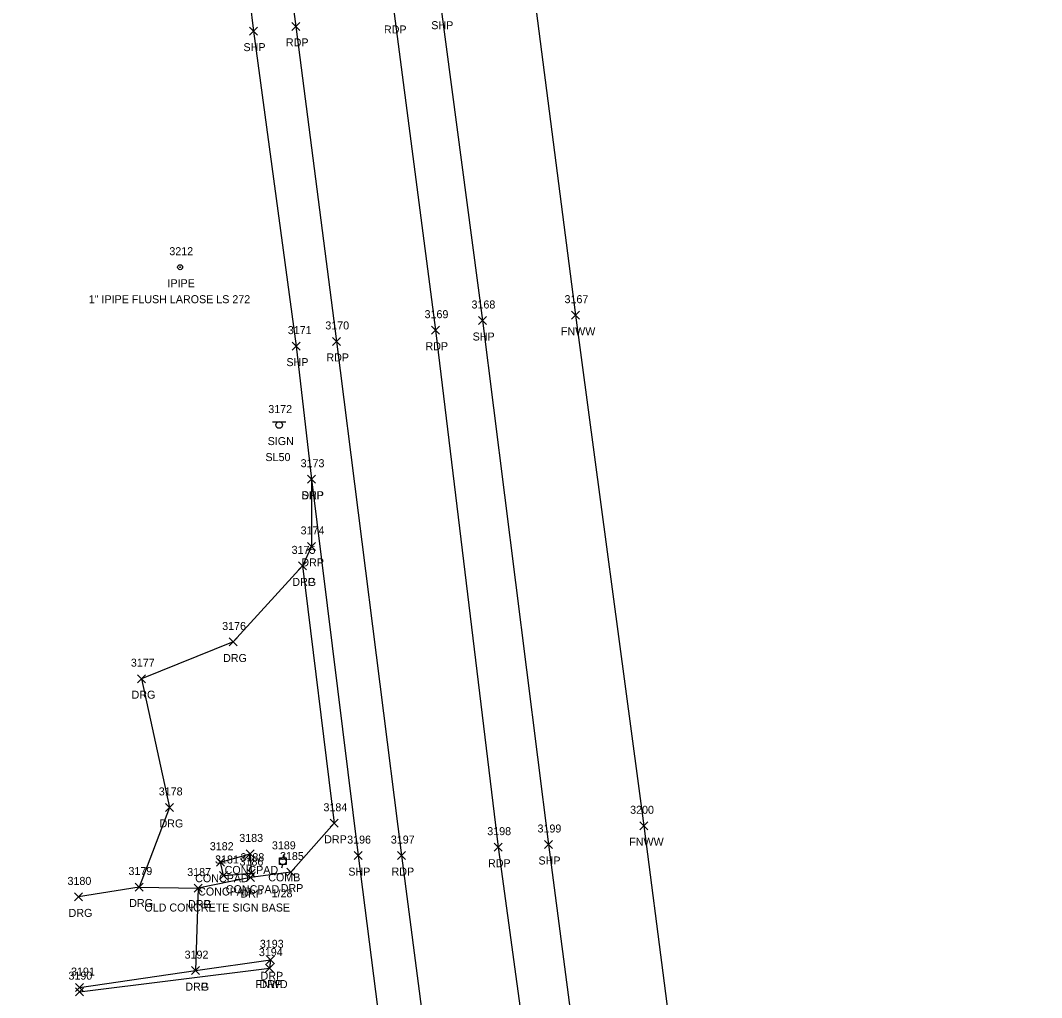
# Model space of a CAD drawing. Extents: x 1443071 to 1445292, y 614024 to 622563.
# Drawn here: x 1444280.5 to 1444535.7, y 616523.8 to 616767.9 of the extents above; entities that cross this region are included whole.
import ezdxf

# ---------------------------------------------------------------- set-up
doc = ezdxf.new("R2010")
doc.units = 0
for name, color, linetype in [('L_A', 7, 'Continuous'), ('L_C', 7, 'Continuous'), ('L_I', 7, 'Continuous'), ('L_TIC', 7, 'Continuous'), ('LFNC', 7, 'Continuous'), ('LS', 7, 'Continuous'), ('M_A', 7, 'Continuous'), ('M_C', 7, 'Continuous'), ('M_I', 7, 'Continuous'), ('MPIP', 7, 'Continuous'), ('P_A', 7, 'Continuous'), ('P_I', 7, 'Continuous'), ('P_TIC', 7, 'Continuous'), ('PET', 7, 'Continuous'), ('PSP', 7, 'Continuous'), ('R_A', 7, 'Continuous'), ('R_I', 7, 'Continuous'), ('R_TIC', 7, 'Continuous'), ('RDG', 7, 'Continuous'), ('RDP', 7, 'Continuous'), ('S_A', 7, 'Continuous'), ('S_C', 7, 'Continuous'), ('S_I', 7, 'Continuous'), ('SSGN', 7, 'Continuous'), ('U_A', 7, 'Continuous'), ('U_C', 7, 'Continuous'), ('U_I', 7, 'Continuous'), ('UP', 7, 'Continuous')]:
    doc.layers.add(name, color=color, linetype=linetype)

msp = doc.modelspace()

# ---------------------------------------------------------------- linework, layer by layer
at = {"layer": 'L_TIC'}
for points in [[(1444418.22, 616693.29), (1444420.22, 616695.29)], [(1444420.22, 616693.29), (1444418.22, 616695.29)], [(1444435.3, 616565.7), (1444437.3, 616567.7)], [(1444437.3, 616565.7), (1444435.3, 616567.7)], [(1444336.88, 616558.67), (1444338.88, 616560.67)], [(1444338.88, 616558.67), (1444336.88, 616560.67)], [(1444329.52, 616556.6), (1444331.52, 616558.6)], [(1444331.52, 616556.6), (1444329.52, 616558.6)], [(1444330.26, 616553.28), (1444332.26, 616555.28)], [(1444332.26, 616553.28), (1444330.26, 616555.28)], [(1444330.26, 616553.28), (1444332.26, 616555.28)], [(1444332.26, 616553.28), (1444330.26, 616555.28)], [(1444337.19, 616553.85), (1444339.19, 616555.85)], [(1444339.19, 616553.85), (1444337.19, 616555.85)], [(1444337.19, 616553.85), (1444339.19, 616555.85)], [(1444339.19, 616553.85), (1444337.19, 616555.85)], [(1444341.78, 616530.14), (1444343.78, 616532.14)], [(1444343.78, 616530.14), (1444341.78, 616532.14)], [(1444294.29, 616524.25), (1444296.29, 616526.25)], [(1444296.29, 616524.25), (1444294.29, 616526.25)]]:
    msp.add_lwpolyline(points, dxfattribs=at)
at = {"layer": 'LFNC'}
for points in [[(1444444.21, 617032.59), (1444396.73, 617023.1), (1444383.68, 617022.43), (1444396.85, 616893.79), (1444402.65, 616848.17), (1444409.06, 616773.1), (1444419.22, 616694.29), (1444436.3, 616566.7), (1444446.44, 616488.05), (1444452.89, 616451.02), (1444456.99, 616417.96)], [(1444295.29, 616525.25), (1444342.78, 616531.14)]]:
    msp.add_lwpolyline(points, dxfattribs=at)
at = {"layer": 'LS'}
for points in [[(1444331.26, 616554.28), (1444330.52, 616557.6), (1444337.88, 616559.67), (1444338.19, 616554.85)], [(1444331.26, 616554.28), (1444338.19, 616554.85)]]:
    msp.add_lwpolyline(points, dxfattribs=at)
at = {"layer": 'MPIP'}
for radius in [0.625, 0.0833]:
    msp.add_circle((1444320.42, 616706.28), radius, dxfattribs=at)
at = {"layer": 'P_TIC'}
for points in [[(1444348.36, 616765.46), (1444350.36, 616767.46)], [(1444350.36, 616765.46), (1444348.36, 616767.46)], [(1444337.72, 616764.27), (1444339.72, 616766.27)], [(1444339.72, 616764.27), (1444337.72, 616766.27)], [(1444394.97, 616691.96), (1444396.97, 616693.96)], [(1444396.97, 616691.96), (1444394.97, 616693.96)], [(1444383.25, 616689.54), (1444385.25, 616691.54)], [(1444385.25, 616689.54), (1444383.25, 616691.54)], [(1444358.48, 616686.73), (1444360.48, 616688.73)], [(1444360.48, 616686.73), (1444358.48, 616688.73)], [(1444348.45, 616685.56), (1444350.45, 616687.56)], [(1444350.45, 616685.56), (1444348.45, 616687.56)], [(1444352.22, 616652.3), (1444354.22, 616654.3)], [(1444354.22, 616652.3), (1444352.22, 616654.3)], [(1444411.43, 616561.03), (1444413.43, 616563.03)], [(1444413.43, 616561.03), (1444411.43, 616563.03)], [(1444398.86, 616560.36), (1444400.86, 616562.36)], [(1444400.86, 616560.36), (1444398.86, 616562.36)], [(1444363.91, 616558.25), (1444365.91, 616560.25)], [(1444365.91, 616558.25), (1444363.91, 616560.25)], [(1444374.76, 616558.26), (1444376.76, 616560.26)], [(1444376.76, 616558.26), (1444374.76, 616560.26)]]:
    msp.add_lwpolyline(points, dxfattribs=at)
at = {"layer": 'PET'}
for points in [[(1444290.04, 617226.49), (1444293.29, 617200.68), (1444305.86, 617102.26), (1444318.1, 617012.36), (1444328.61, 616929.53), (1444340.48, 616832.7), (1444349.36, 616766.46), (1444359.48, 616687.73), (1444375.76, 616559.26), (1444386.72, 616474.82), (1444392.98, 616424.11), (1444399.64, 616374.74), (1444405.35, 616331.68), (1444416.25, 616246.74), (1444430.45, 616134.64), (1444440.68, 616052.2), (1444460.71, 615897.87), (1444469.48, 615825.17), (1444479.32, 615749.85), (1444490.82, 615663.43), (1444501.1, 615593.99)], [(1444314.9, 617227.6), (1444331.28, 617099.37), (1444342.74, 617014.98), (1444353.45, 616933.43), (1444365.99, 616834.42), (1444373.87, 616769.68), (1444384.25, 616690.54), (1444399.86, 616561.36), (1444411.32, 616477.78), (1444418.43, 616426.72), (1444433.04, 616320.39), (1444440.5, 616248.61), (1444455.15, 616137.88), (1444465.57, 616054.84), (1444485.3, 615900.9), (1444494.14, 615826.26), (1444503.74, 615751.94), (1444515.41, 615666.64), (1444525.64, 615597.72)]]:
    msp.add_lwpolyline(points, dxfattribs=at)
at = {"layer": 'PSP'}
for points in [[(1444325.72, 617229.34), (1444331.18, 617190.03), (1444341.63, 617111.11), (1444353.65, 617016.1), (1444364.55, 616934.22), (1444377.14, 616835.48), (1444385.64, 616770.75), (1444395.97, 616692.96), (1444412.43, 616562.03), (1444423.01, 616481.11), (1444430.88, 616420.51), (1444443.11, 616323.39), (1444448.99, 616268.44), (1444454, 616230.8), (1444465.61, 616141.36), (1444476.5, 616056.13), (1444483.28, 615998.72), (1444489.46, 615946.55), (1444495.54, 615902.14), (1444505.18, 615827.19), (1444514.81, 615753.2), (1444525.85, 615667.7), (1444535.69, 615600.77)], [(1444280.5, 617226.12), (1444283.66, 617200.61), (1444293.17, 617127.11), (1444296.38, 617100.83), (1444308.28, 617010.91), (1444318.74, 616928.98), (1444325.56, 616872.02), (1444335.05, 616795.34), (1444338.72, 616765.27), (1444349.45, 616686.56), (1444353.22, 616653.3), (1444364.91, 616559.25), (1444375.85, 616473.62), (1444383.24, 616422.24), (1444388.01, 616382.64), (1444395.12, 616329.81), (1444406.01, 616244.88), (1444420.16, 616134.13), (1444430.49, 616051.12), (1444450.17, 615896.86), (1444459.96, 615823.48), (1444469.66, 615749), (1444481.34, 615661.86), (1444491.6, 615592.34)]]:
    msp.add_lwpolyline(points, dxfattribs=at)
at = {"layer": 'R_TIC'}
for points in [[(1444352.22, 616652.3), (1444354.22, 616654.3)], [(1444354.22, 616652.3), (1444352.22, 616654.3)], [(1444352.22, 616635.51), (1444354.22, 616637.51)], [(1444354.22, 616635.51), (1444352.22, 616637.51)], [(1444349.96, 616630.64), (1444351.96, 616632.64)], [(1444351.96, 616630.64), (1444349.96, 616632.64)], [(1444349.96, 616630.64), (1444351.96, 616632.64)], [(1444351.96, 616630.64), (1444349.96, 616632.64)], [(1444332.67, 616611.63), (1444334.67, 616613.63)], [(1444334.67, 616611.63), (1444332.67, 616613.63)], [(1444309.79, 616602.46), (1444311.79, 616604.46)], [(1444311.79, 616602.46), (1444309.79, 616604.46)], [(1444316.77, 616570.29), (1444318.77, 616572.29)], [(1444318.77, 616570.29), (1444316.77, 616572.29)], [(1444357.93, 616566.33), (1444359.93, 616568.33)], [(1444359.93, 616566.33), (1444357.93, 616568.33)], [(1444347.07, 616554.14), (1444349.07, 616556.14)], [(1444349.07, 616554.14), (1444347.07, 616556.14)], [(1444337.01, 616552.76), (1444339.01, 616554.76)], [(1444339.01, 616552.76), (1444337.01, 616554.76)], [(1444309.2, 616550.4), (1444311.2, 616552.4)], [(1444311.2, 616550.4), (1444309.2, 616552.4)], [(1444309.2, 616550.4), (1444311.2, 616552.4)], [(1444311.2, 616550.4), (1444309.2, 616552.4)], [(1444323.89, 616550.15), (1444325.89, 616552.15)], [(1444325.89, 616550.15), (1444323.89, 616552.15)], [(1444323.89, 616550.15), (1444325.89, 616552.15)], [(1444325.89, 616550.15), (1444323.89, 616552.15)], [(1444294.05, 616547.93), (1444296.05, 616549.93)], [(1444296.05, 616547.93), (1444294.05, 616549.93)], [(1444342.03, 616532.21), (1444344.03, 616534.21)], [(1444344.03, 616532.21), (1444342.03, 616534.21)], [(1444323.22, 616529.51), (1444325.22, 616531.51)], [(1444325.22, 616529.51), (1444323.22, 616531.51)], [(1444323.22, 616529.51), (1444325.22, 616531.51)], [(1444325.22, 616529.51), (1444323.22, 616531.51)], [(1444341.78, 616530.14), (1444343.78, 616532.14)], [(1444343.78, 616530.14), (1444341.78, 616532.14)], [(1444294.28, 616525.27), (1444296.28, 616527.27)], [(1444296.28, 616525.27), (1444294.28, 616527.27)]]:
    msp.add_lwpolyline(points, dxfattribs=at)
at = {"layer": 'RDG'}
for points in [[(1444350.96, 616631.64), (1444333.67, 616612.63), (1444310.79, 616603.46), (1444317.77, 616571.29), (1444310.2, 616551.4), (1444324.89, 616551.15)], [(1444310.2, 616551.4), (1444295.05, 616548.93)], [(1444295.28, 616526.27), (1444324.22, 616530.51)]]:
    msp.add_lwpolyline(points, dxfattribs=at)
at = {"layer": 'RDP'}
msp.add_lwpolyline([(1444353.22, 616653.3), (1444353.22, 616636.51), (1444350.96, 616631.64), (1444358.93, 616567.33), (1444348.07, 616555.14), (1444338.01, 616553.76), (1444324.89, 616551.15), (1444324.22, 616530.51), (1444343.03, 616533.21), (1444342.78, 616531.14)], dxfattribs=at)
at = {"layer": 'SSGN'}
for p, q in [((1444343.5, 616667.68), (1444346.84, 616667.68)), ((1444345.15, 616666.85), (1444345.15, 616666.85))]:
    msp.add_line(p, q, dxfattribs=at)
msp.add_circle((1444345.15, 616666.85), 0.833, dxfattribs=at)
at = {"layer": 'UP'}
for p, q in [((1444345.21, 616556.99), (1444345.21, 616558.66)), ((1444345.21, 616558.66), (1444346.88, 616558.66)), ((1444346.3, 616559.49), (1444346.05, 616558.66)), ((1444346.05, 616557.82), (1444346.05, 616557.82)), ((1444346.88, 616558.66), (1444346.88, 616556.99)), ((1444346.88, 616556.99), (1444345.21, 616556.99)), ((1444345.8, 616556.16), (1444346.05, 616556.99))]:
    msp.add_line(p, q, dxfattribs=at)
msp.add_circle((1444346.05, 616557.82), 0.833, dxfattribs=at)

# ---------------------------------------------------------------- texts
at = {"layer": 'L_A'}
for s, p in [('FNWW', (1444415.57, 616689.29)), ('FNWW', (1444432.64, 616561.7)), ('CONCPAD', (1444331.53, 616554.67)), ('CONCPAD', (1444324.17, 616552.6)), ('CONCPAD', (1444324.91, 616549.28)), ('CONCPAD', (1444324.91, 616549.28)), ('CONCPAD', (1444331.83, 616549.85)), ('CONCPAD', (1444331.83, 616549.85)), ('FNWD', (1444339.25, 616526.14))]:
    msp.add_text(s, height=2, dxfattribs=at).set_placement(p)
at = {"layer": 'L_C'}
msp.add_text('OLD CONCRETE SIGN BASE', height=2, dxfattribs=at).set_placement((1444311.48, 616545.28))
msp.add_text('OLD CONCRETE SIGN BASE', height=2, dxfattribs=at).set_placement((1444311.48, 616545.28))
at = {"layer": 'L_I'}
for s, p in [('3167', (1444416.48, 616697.29)), ('3200', (1444432.87, 616569.7)), ('3183', (1444335.19, 616562.67)), ('3182', (1444327.83, 616560.6)), ('3181', (1444329.14, 616557.28)), ('3181', (1444329.14, 616557.28)), ('3188', (1444335.49, 616557.85)), ('3188', (1444335.49, 616557.85)), ('3194', (1444340.09, 616534.14)), ('3190', (1444292.51, 616528.25))]:
    msp.add_text(s, height=2, dxfattribs=at).set_placement(p)
at = {"layer": 'M_A'}
msp.add_text('IPIPE', height=2, dxfattribs=at).set_placement((1444317.25, 616701.28))
at = {"layer": 'M_C'}
msp.add_text('1" IPIPE FLUSH LAROSE LS 272', height=2, dxfattribs=at).set_placement((1444297.58, 616697.28))
at = {"layer": 'M_I'}
msp.add_text('3212', height=2, dxfattribs=at).set_placement((1444317.72, 616709.28))
at = {"layer": 'P_A'}
for s, p in [('SHP', (1444383.17, 616765.75)), ('RDP', (1444371.35, 616764.68)), ('SHP', (1444336.25, 616760.27)), ('RDP', (1444346.85, 616761.46)), ('SHP', (1444393.51, 616687.96)), ('RDP', (1444381.73, 616685.54)), ('SHP', (1444346.98, 616681.56)), ('RDP', (1444356.97, 616682.73)), ('SHP', (1444350.76, 616648.3)), ('RDP', (1444397.35, 616556.36)), ('SHP', (1444409.97, 616557.03)), ('SHP', (1444362.45, 616554.25)), ('RDP', (1444373.25, 616554.26))]:
    msp.add_text(s, height=2, dxfattribs=at).set_placement(p)
at = {"layer": 'P_I'}
for s, p in [('3169', (1444381.5, 616693.54)), ('3168', (1444393.23, 616695.96)), ('3171', (1444347.32, 616689.56)), ('3170', (1444356.7, 616690.73)), ('3173', (1444350.53, 616656.3)), ('3198', (1444397.17, 616564.36)), ('3199', (1444409.73, 616565.03)), ('3196', (1444362.16, 616562.25)), ('3197', (1444373.07, 616562.26))]:
    msp.add_text(s, height=2, dxfattribs=at).set_placement(p)
at = {"layer": 'R_A'}
for s, p in [('DRP', (1444350.71, 616648.3)), ('DRP', (1444350.7, 616631.51)), ('DRG', (1444348.45, 616626.64)), ('DRP', (1444348.45, 616626.64)), ('DRG', (1444331.15, 616607.63)), ('DRG', (1444308.28, 616598.46)), ('DRG', (1444315.26, 616566.29)), ('DRP', (1444356.41, 616562.33)), ('DRP', (1444335.49, 616548.76)), ('DRP', (1444345.55, 616550.14)), ('DRG', (1444307.69, 616546.4)), ('DRG', (1444307.69, 616546.4)), ('DRG', (1444322.37, 616546.15)), ('DRP', (1444322.37, 616546.15)), ('DRG', (1444292.54, 616543.93)), ('DRP', (1444340.52, 616528.21)), ('DRG', (1444321.71, 616525.51)), ('DRP', (1444321.71, 616525.51)), ('DRP', (1444340.27, 616526.14))]:
    msp.add_text(s, height=2, dxfattribs=at).set_placement(p)
at = {"layer": 'R_I'}
for s, p in [('3173', (1444350.53, 616656.3)), ('3174', (1444350.52, 616639.51)), ('3175', (1444348.27, 616634.64)), ('3175', (1444348.27, 616634.64)), ('3176', (1444330.92, 616615.63)), ('3177', (1444308.1, 616606.46)), ('3178', (1444315.08, 616574.29)), ('3184', (1444356.23, 616570.33)), ('3186', (1444335.26, 616556.76)), ('3185', (1444345.37, 616558.14)), ('3179', (1444307.5, 616554.4)), ('3179', (1444307.5, 616554.4)), ('3187', (1444322.19, 616554.15)), ('3187', (1444322.19, 616554.15)), ('3180', (1444292.27, 616551.93)), ('3193', (1444340.33, 616536.21)), ('3192', (1444321.53, 616533.51)), ('3192', (1444321.53, 616533.51)), ('3194', (1444340.09, 616534.14)), ('3191', (1444293.15, 616529.27))]:
    msp.add_text(s, height=2, dxfattribs=at).set_placement(p)
at = {"layer": 'S_A'}
msp.add_text('SIGN', height=2, dxfattribs=at).set_placement((1444342.29, 616661.83))
at = {"layer": 'S_C'}
msp.add_text('SL50', height=2, dxfattribs=at).set_placement((1444341.74, 616657.83))
at = {"layer": 'S_I'}
msp.add_text('3172', height=2, dxfattribs=at).set_placement((1444342.44, 616669.83))
at = {"layer": 'U_A'}
msp.add_text('COMB', height=2, dxfattribs=at).set_placement((1444342.43, 616552.82))
at = {"layer": 'U_C'}
msp.add_text('1/28', height=2, dxfattribs=at).set_placement((1444343.28, 616548.82))
at = {"layer": 'U_I'}
msp.add_text('3189', height=2, dxfattribs=at).set_placement((1444343.35, 616560.82))

doc.saveas('drawing.dxf')
